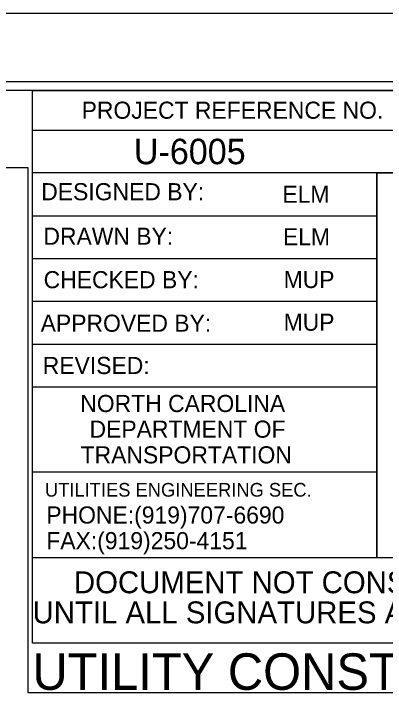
# Model space of a CAD drawing. Extents: x 0 to 2694, y -1 to 1501.
# Drawn here: x 2.4627 to 2.644, y 1.5026 to 1.8333 of the extents above; entities that cross this region are included whole.
import ezdxf

# ---------------------------------------------------------------- set-up
doc = ezdxf.new("R2010")
doc.units = 0
for name, color, linetype in [('Air Release (M1) CELL', 7, 'Continuous'), ('Air Release (M2) CELL', 7, 'Continuous'), ('Air Release (St) CELL', 7, 'Continuous'), ('COGO Default Point Elevation', 7, 'Continuous')]:
    doc.layers.add(name, color=color, linetype=linetype)

msp = doc.modelspace()

# ---------------------------------------------------------------- linework, layer by layer
at = {"layer": 'Air Release (M1) CELL'}
msp.add_lwpolyline([(0.30746, 0.89289), (0.30758, 1.69779), (0.7284, 1.69769), (0.7284, 1.75822), (2.46973, 1.75822), (2.46973, 1.50207), (2.7791, 1.50207), (2.78092, 1.04749), (2.27463, 1.04778), (2.27347, 0.89289)], close=True, dxfattribs=at)
at = {"layer": 'Air Release (M2) CELL'}
for p, q in [((2.4719, 1.77648), (2.80496, 1.77648)), ((2.55581, 1.76604), (2.55581, 1.76604)), ((2.6054, 1.74516), (2.6054, 1.74516)), ((2.4719, 1.7347), (2.63979, 1.7347)), ((2.6054, 1.72427), (2.6054, 1.72427)), ((2.4719, 1.71383), (2.63979, 1.71383)), ((2.6054, 1.70339), (2.6054, 1.70339)), ((2.4719, 1.69295), (2.63979, 1.69295)), ((2.6054, 1.68252), (2.6054, 1.68252)), ((2.4719, 1.67208), (2.63979, 1.67208)), ((2.4719, 1.65118), (2.63979, 1.65118)), ((2.4719, 1.60977), (2.63979, 1.60977))]:
    msp.add_line(p, q, dxfattribs=at)
for points in [[(2.4719, 1.79581), (2.80496, 1.79581), (2.80496, 1.75568)], [(2.80496, 1.75568), (2.4719, 1.75568), (2.4719, 1.79581)], [(2.63979, 1.75568), (2.63979, 1.56775), (2.4719, 1.56775), (2.4719, 1.79581)], [(2.80496, 1.56775), (2.63979, 1.56775), (2.63979, 1.7556), (2.80496, 1.7556)]]:
    msp.add_lwpolyline(points, dxfattribs=at)
at = {"layer": 'COGO Default Point Elevation'}
for p, q in [((2.60044, 1.74676), (2.60044, 1.74676)), ((2.4719, 1.52621), (2.4719, 1.56775)), ((2.80496, 1.52621), (2.4719, 1.52621))]:
    msp.add_line(p, q, dxfattribs=at)
for points in [[(0.02749, 0.00833), (2.83333, 0.00833), (2.83333, 1.83333), (0.02749, 1.83333)], [(0.04916, 0.04166), (2.82583, 0.04166), (2.82583, 1.8), (0.04916, 1.8)], [(2.80499, 1.79583), (0.30499, 1.79583), (0.30499, 0.04583), (2.80499, 0.04583)]]:
    msp.add_lwpolyline(points, close=True, dxfattribs=at)

# ---------------------------------------------------------------- texts
at = {"layer": 'Air Release (M2) CELL'}
for s, height, p in [('PROJECT REFERENCE NO.', 0.0083524, (2.4959, 1.782)), ('DESIGNED BY:', 0.0083524, (2.47619, 1.74223)), ('DRAWN BY:', 0.008352, (2.47727, 1.72052)), ('CHECKED BY:', 0.0083524, (2.47736, 1.69931)), ('APPROVED BY:', 0.0083524, (2.47592, 1.67808)), ('REVISED:', 0.008352, (2.47694, 1.65745)), ('NORTH CAROLINA', 0.0083524, (2.49523, 1.63891)), ('DEPARTMENT OF', 0.0083524, (2.49975, 1.62639)), ('TRANSPORTATION', 0.0083524, (2.4954, 1.61385)), ('UTILITIES ENGINEERING SEC.', 0.0066819, (2.47799, 1.59763)), ('PHONE:(919)707-6690', 0.0083524, (2.47867, 1.58451)), ('FAX:(919)250-4151', 0.0083524, (2.47867, 1.57199))]:
    msp.add_text(s, height=height, dxfattribs=at).set_placement(p)
at = {"layer": 'Air Release (St) CELL'}
for s, p in [('DOCUMENT NOT CONSIDERED FINAL ', (2.49215, 1.5505)), ('UNTIL ALL SIGNATURES ARE COMPLETED', (2.47197, 1.53581))]:
    msp.add_text(s, height=0.010697, dxfattribs=at).set_placement(p)
at = {"layer": 'COGO Default Point Elevation'}
for s, height, p in [('U-6005', 0.01243, (2.52136, 1.75982)), ('ELM', 0.008333, (2.59379, 1.74103)), ('ELM', 0.008333, (2.59408, 1.72025)), ('MUP', 0.008333, (2.59442, 1.69941)), ('MUP', 0.008333, (2.59442, 1.67858)), ('UTILITY CONSTRUCTION', 0.0178124, (2.4719, 1.50337))]:
    msp.add_text(s, height=height, dxfattribs=at).set_placement(p)

doc.saveas('drawing.dxf')
